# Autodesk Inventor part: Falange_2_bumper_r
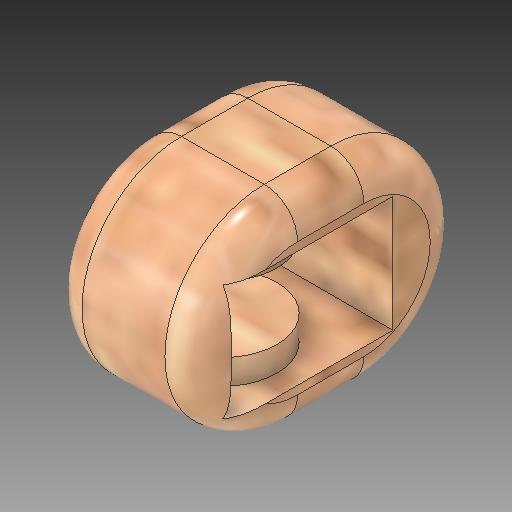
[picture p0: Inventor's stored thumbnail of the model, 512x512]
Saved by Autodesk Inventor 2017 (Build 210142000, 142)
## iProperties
Created: 2017-05
Part Number: Falange_2_bumper_r
Material: Generic
Document SubType Name: Modeling
Designer: alez_
Density: 1 g/cm^3
Appearance: Default
Author: alez_
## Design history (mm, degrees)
derived "Falange_2_bumper.ipt" dims "d0" = 11
feature "Solid1::Falange_2_bumper.ipt" dims "d0" = 11
tag "TaggingFeature1"
body "Solid1"
